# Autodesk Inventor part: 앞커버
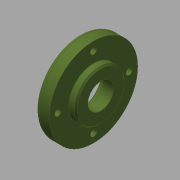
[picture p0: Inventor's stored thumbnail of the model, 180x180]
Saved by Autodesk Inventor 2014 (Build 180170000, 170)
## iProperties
Created: 2015-12
Part Number: 앞커버
Document SubType Name: Modeling
Designer: mdu
Density: 2.71 g/cm^3
Material: 알루미늄 6061
Appearance: 알루미늄 - 평지
Mass: 70.9292 g
Surface Area: 93.9278 cm^2
Volume: 26.1731 cm^3
Author: mdu
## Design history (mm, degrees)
sketch "스케치1"
  geometry: L1 (-7.5, 0)-(7.5, 0); L2 (-7.5, 0)-(-7.5, 31); L3 (-7.5, 31)-(2.5, 31); L4 (2.5, 31)-(2.5, 17.5); L5 (2.5, 17.5)-(7.5, 17.5); L6 (7.5, 17.5)-(7.5, 0); 2 further points
  constraints: 12 end point, 3 perpendicular, 1 coincident, 1 horizontal, 1 midpoint, 1 parallel
  dimensions: "d0" = 15 distance of L1.start L1.end; "d1" = 62 diameter of L3 L1; "d2" = 35 diameter of L5 L1; "d5" = 10 distance of L2.end L3.end
revolve "회전1" sketch "스케치1" stored, may be unused: angle "d6" = 90 deg
sketch "스케치2" dims "d42" = 50
  geometry: 3 further points
  constraints: 2 vertical alignment, 1 coincident, 2 other
hole "구멍1" sketch "스케치2" at (0, 25) diameter "d8" = 4.5; stored, may be unused: countersink angle "d12" = 90 deg, drill point angle "d14" = 118 deg; dims "d9" = 6, "d10" = 8, "d11" = 4.4, "d13" = 8
hole "구멍2" diameter "d20" = 18; stored, may be unused: countersink angle "d24" = 90 deg, drill point angle "d26" = 0 deg; dims "d18" = 10, "d19" = 10, "d21" = 6, "d22" = 8, "d23" = 4.4, "d25" = 8
hole "구멍3" diameter "d34" = 30; stored, may be unused: countersink angle "d38" = 90 deg, drill point angle "d40" = 0 deg; dims "d32" = 10, "d33" = 10, "d35" = 6, "d36" = 4, "d37" = 2, "d39" = 7.3
fillet "모깎기1" dims "d27" = 3, "d41" = 0.3
chamfer "모따기1" distance "d29" = 1; stored, may be unused: second distance "d30" = 2, angle "d31" = 45 deg
node "솔리드1"
pattern_circular "원형 패턴1" dims angle "d16" = 360 deg
